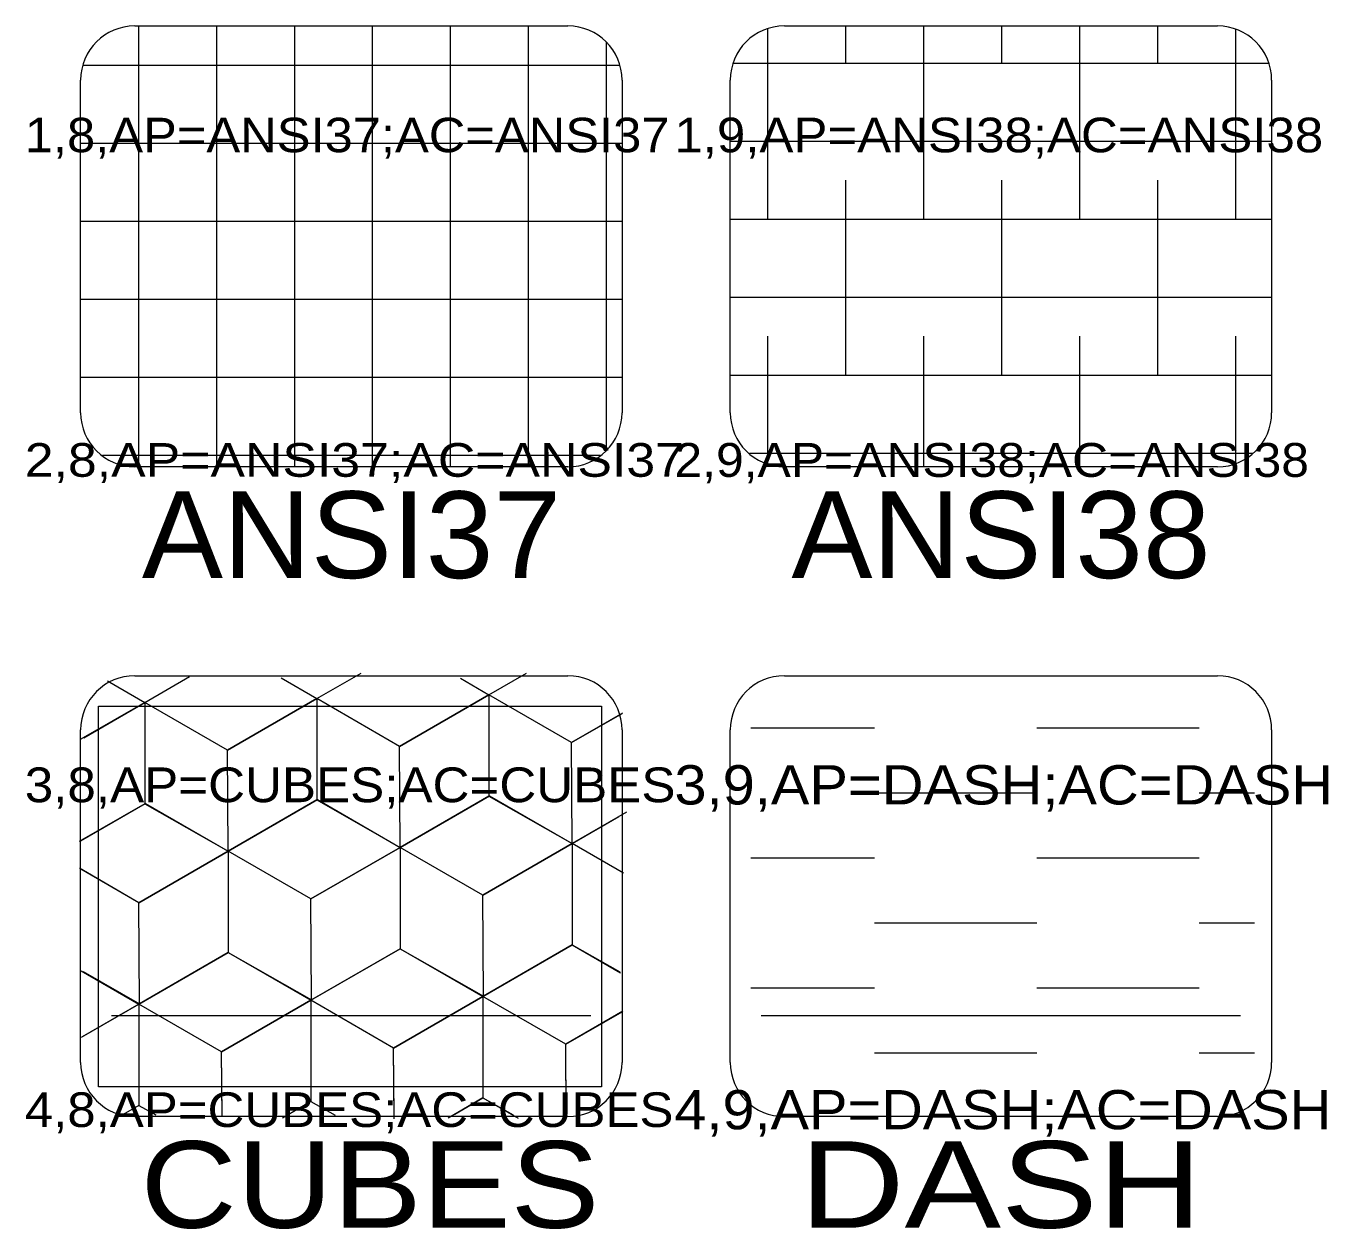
# Model space of a CAD drawing. Extents: x 95935 to 95946.4, y 95971.2 to 95974.7.
# Drawn here: x 95939.235 to 95940.433, y 95973.621 to 95974.732 of the extents above; entities that cross this region are included whole.
import ezdxf
from ezdxf.enums import TextEntityAlignment as Align

# ---------------------------------------------------------------- set-up
doc = ezdxf.new("R2010")
doc.units = 0
doc.header["$LTSCALE"] = 0.013
for name, color, linetype, lineweight in [('1', 7, 'Continuous', 13), ('25', 7, 'Continuous', 13), ('6', 7, 'Continuous', 13), ('63', 7, 'Continuous', 13)]:
    doc.layers.add(name, color=color, linetype=linetype, lineweight=lineweight)
doc.layers.add('20', color=7, linetype='Continuous')

msp = doc.modelspace()

# ---------------------------------------------------------------- linework, layer by layer
at = {"layer": '1'}
for p, q in [((95939.3357, 95974.7318), (95939.7357, 95974.7318)), ((95939.9357, 95974.7318), (95940.3357, 95974.7318)), ((95939.2857, 95974.3747), (95939.2857, 95974.6818)), ((95939.7857, 95974.6818), (95939.7857, 95974.3747)), ((95939.8857, 95974.3747), (95939.8857, 95974.6818)), ((95940.3857, 95974.6818), (95940.3857, 95974.3747)), ((95939.7357, 95974.3247), (95939.3357, 95974.3247)), ((95940.3357, 95974.3247), (95939.9357, 95974.3247)), ((95939.3357, 95974.1318), (95939.7357, 95974.1318)), ((95939.9357, 95974.1318), (95940.3357, 95974.1318)), ((95939.2857, 95973.7747), (95939.2857, 95974.0818)), ((95939.7857, 95974.0818), (95939.7857, 95973.7747)), ((95939.8857, 95973.7747), (95939.8857, 95974.0818)), ((95940.3857, 95974.0818), (95940.3857, 95973.7747)), ((95939.7357, 95973.7247), (95939.3357, 95973.7247)), ((95940.3357, 95973.7247), (95939.9357, 95973.7247))]:
    msp.add_line(p, q, dxfattribs=at)
for centre, start, end in [((95939.3357, 95974.6818), 90, 180), ((95939.7357, 95974.6818), 0, 90), ((95939.9357, 95974.6818), 90, 180), ((95940.3357, 95974.6818), 0, 90), ((95939.3357, 95974.3747), 180, 270), ((95939.7357, 95974.3747), 270, 0), ((95939.9357, 95974.3747), 180, 270), ((95940.3357, 95974.3747), 270, 0), ((95939.3357, 95974.0818), 90, 180), ((95939.7357, 95974.0818), 0, 90), ((95939.9357, 95974.0818), 90, 180), ((95940.3357, 95974.0818), 0, 90), ((95939.3357, 95973.7747), 180, 270), ((95939.7357, 95973.7747), 270, 0), ((95939.9357, 95973.7747), 180, 270), ((95940.3357, 95973.7747), 270, 0)]:
    msp.add_arc(centre, 0.05, start, end, dxfattribs=at)
at = {"layer": '25'}
for p, q in [((95939.7569, 95973.8178), (95939.3141, 95973.8178)), ((95940.3569, 95973.8178), (95939.9141, 95973.8178))]:
    msp.add_line(p, q, dxfattribs=at)
at = {"layer": '6'}
for p, q in [((95939.3391, 95974.7318), (95939.3391, 95974.3247)), ((95939.4111, 95974.7318), (95939.4111, 95974.3247)), ((95939.4831, 95974.7318), (95939.4831, 95974.3247)), ((95939.5551, 95974.7318), (95939.5551, 95974.3247)), ((95939.6271, 95974.7318), (95939.6271, 95974.3247)), ((95939.6991, 95974.7318), (95939.6991, 95974.3247)), ((95939.9205, 95974.6973), (95939.9205, 95974.7288)), ((95939.9925, 95974.6973), (95939.9925, 95974.7318)), ((95940.0645, 95974.6973), (95940.0645, 95974.7318)), ((95940.1365, 95974.6973), (95940.1365, 95974.7318)), ((95940.2085, 95974.6973), (95940.2085, 95974.7318)), ((95940.2805, 95974.6973), (95940.2805, 95974.7318)), ((95940.3525, 95974.6973), (95940.3525, 95974.7285)), ((95939.7711, 95974.7172), (95939.7711, 95974.3393)), ((95939.2884, 95974.6956), (95939.783, 95974.6956)), ((95939.8888, 95974.6973), (95940.3826, 95974.6973)), ((95939.9205, 95974.5533), (95939.9205, 95974.6973)), ((95940.0645, 95974.5533), (95940.0645, 95974.6973)), ((95940.2085, 95974.5533), (95940.2085, 95974.6973)), ((95940.3525, 95974.5533), (95940.3525, 95974.6973)), ((95939.2857, 95974.6236), (95939.7857, 95974.6236)), ((95939.8857, 95974.6253), (95940.3857, 95974.6253)), ((95939.9925, 95974.4093), (95939.9925, 95974.5893)), ((95940.1365, 95974.4093), (95940.1365, 95974.5893)), ((95940.2805, 95974.4093), (95940.2805, 95974.5893)), ((95939.2857, 95974.5516), (95939.7857, 95974.5516)), ((95939.8857, 95974.5533), (95940.3857, 95974.5533)), ((95939.2857, 95974.4796), (95939.7857, 95974.4796)), ((95939.8857, 95974.4813), (95940.3857, 95974.4813)), ((95939.9205, 95974.4093), (95939.9205, 95974.4453)), ((95940.0645, 95974.4093), (95940.0645, 95974.4453)), ((95940.2085, 95974.4093), (95940.2085, 95974.4453)), ((95940.3525, 95974.4093), (95940.3525, 95974.4453)), ((95939.2857, 95974.4076), (95939.7857, 95974.4076)), ((95939.8857, 95974.4093), (95940.3857, 95974.4093)), ((95939.9205, 95974.3277), (95939.9205, 95974.4093)), ((95940.0645, 95974.3247), (95940.0645, 95974.4093)), ((95940.2085, 95974.3247), (95940.2085, 95974.4093)), ((95940.3525, 95974.328), (95940.3525, 95974.4093)), ((95939.3059, 95974.3356), (95939.7655, 95974.3356)), ((95939.9033, 95974.3373), (95940.3681, 95974.3373)), ((95939.9048, 95974.0836), (95940.0189, 95974.0836)), ((95940.1689, 95974.0836), (95940.3189, 95974.0836)), ((95940.0189, 95974.0236), (95940.1689, 95974.0236)), ((95940.3189, 95974.0236), (95940.37, 95974.0236)), ((95939.9048, 95973.9636), (95940.0189, 95973.9636)), ((95940.1689, 95973.9636), (95940.3189, 95973.9636)), ((95940.0189, 95973.9036), (95940.1689, 95973.9036)), ((95940.3189, 95973.9036), (95940.37, 95973.9036)), ((95939.9048, 95973.8436), (95940.0189, 95973.8436)), ((95940.1689, 95973.8436), (95940.3189, 95973.8436)), ((95940.0189, 95973.7836), (95940.1689, 95973.7836)), ((95940.3189, 95973.7836), (95940.37, 95973.7836))]:
    msp.add_line(p, q, dxfattribs=at)
for points in [[(95939.3105, 95974.1272), (95939.345, 95974.1072), (95939.2858, 95974.0731)], [(95939.4709, 95974.1298), (95939.5039, 95974.1107), (95939.4214, 95974.0631), (95939.345, 95974.1072), (95939.3863, 95974.131)], [(95939.6366, 95974.1294), (95939.6628, 95974.1142), (95939.5803, 95974.0666), (95939.5039, 95974.1107), (95939.5447, 95974.1343)], [(95939.786, 95974.0972), (95939.7392, 95974.0701), (95939.6628, 95974.1142), (95939.6974, 95974.1342)], [(95939.2885, 95974.0746), (95939.345, 95974.1072), (95939.345, 95974.0136), (95939.2844, 95973.9787)], [(95939.7897, 95974.0057), (95939.7398, 95973.9768), (95939.7392, 95974.0701), (95939.7858, 95974.097)], [(95939.2858, 95973.9794), (95939.3456, 95974.0139), (95939.422, 95973.9698), (95939.3395, 95973.9222), (95939.2858, 95973.9532)], [(95939.7872, 95973.9495), (95939.7398, 95973.9768), (95939.7829, 95974.0017)], [(95939.7845, 95973.951), (95939.7398, 95973.9768), (95939.7398, 95973.8832), (95939.7838, 95973.8583)], [(95939.2879, 95973.8587), (95939.3401, 95973.8289), (95939.3395, 95973.9222), (95939.2845, 95973.954)], [(95939.7866, 95973.8221), (95939.7337, 95973.7915), (95939.6573, 95973.8356), (95939.7398, 95973.8832), (95939.7844, 95973.8575)], [(95939.2863, 95973.8594), (95939.3395, 95973.8286), (95939.2872, 95973.7985)], [(95939.2864, 95973.798), (95939.3395, 95973.8286), (95939.3395, 95973.735), (95939.325, 95973.7266)], [(95939.4164, 95973.7261), (95939.4159, 95973.7845), (95939.3395, 95973.8286), (95939.3395, 95973.735), (95939.355, 95973.7263)], [(95939.4164, 95973.7245), (95939.4159, 95973.7845), (95939.4984, 95973.8321), (95939.4984, 95973.7385), (95939.4722, 95973.7234)], [(95939.5753, 95973.7261), (95939.5748, 95973.788), (95939.4984, 95973.8321), (95939.4984, 95973.7385), (95939.5207, 95973.7259)], [(95939.5753, 95973.7225), (95939.5748, 95973.788), (95939.6573, 95973.8356), (95939.6573, 95973.742), (95939.625, 95973.7234)], [(95939.7342, 95973.7261), (95939.7337, 95973.7915), (95939.6573, 95973.8356), (95939.6573, 95973.742), (95939.6853, 95973.7262)], [(95939.7342, 95973.7243), (95939.7337, 95973.7915), (95939.7857, 95973.8215)], [(95939.6313, 95973.727), (95939.6573, 95973.742), (95939.6898, 95973.7233)]]:
    msp.add_lwpolyline(points, dxfattribs=at)
for points in [[(95939.5803, 95974.0666), (95939.6628, 95974.1142), (95939.6628, 95974.0206), (95939.5809, 95973.9733)], [(95939.7392, 95974.0701), (95939.6628, 95974.1142), (95939.6628, 95974.0206), (95939.7398, 95973.9768)], [(95939.3021, 95974.1038), (95939.7667, 95974.1038), (95939.7667, 95973.7523), (95939.3021, 95973.7523)], [(95939.4214, 95974.0631), (95939.345, 95974.1072), (95939.345, 95974.0136), (95939.422, 95973.9698)], [(95939.4214, 95974.0631), (95939.5039, 95974.1107), (95939.5039, 95974.0171), (95939.422, 95973.9698)], [(95939.5803, 95974.0666), (95939.5039, 95974.1107), (95939.5039, 95974.0171), (95939.5809, 95973.9733)], [(95939.5809, 95973.9733), (95939.6634, 95974.0209), (95939.7398, 95973.9768), (95939.6573, 95973.9292)], [(95939.422, 95973.9698), (95939.5045, 95974.0174), (95939.5809, 95973.9733), (95939.4984, 95973.9257)], [(95939.4984, 95973.9257), (95939.5809, 95973.9733), (95939.5809, 95973.8797), (95939.499, 95973.8324)], [(95939.6573, 95973.9292), (95939.5809, 95973.9733), (95939.5809, 95973.8797), (95939.6579, 95973.8359)], [(95939.6573, 95973.9292), (95939.7398, 95973.9768), (95939.7398, 95973.8832), (95939.6579, 95973.8359)], [(95939.3395, 95973.9222), (95939.422, 95973.9698), (95939.422, 95973.8762), (95939.3401, 95973.8289)], [(95939.4984, 95973.9257), (95939.422, 95973.9698), (95939.422, 95973.8762), (95939.499, 95973.8324)], [(95939.3395, 95973.8286), (95939.422, 95973.8762), (95939.4984, 95973.8321), (95939.4159, 95973.7845)], [(95939.4984, 95973.8321), (95939.5809, 95973.8797), (95939.6573, 95973.8356), (95939.5748, 95973.788)]]:
    msp.add_lwpolyline(points, close=True, dxfattribs=at)

# ---------------------------------------------------------------- texts
at = {"layer": '20'}
for s, width, p in [('ANSI37', 1.05, (95939.5358, 95974.222)), ('ANSI38', 1.05, (95940.1357, 95974.222)), (' CUBES', 1.15, (95939.5358, 95973.622)), (' DASH ', 1.25, (95940.1358, 95973.622))]:
    msp.add_text(s, height=0.08, dxfattribs=dict(at, width=width)).set_placement(p, align=Align.CENTER)
at = {"layer": '63'}
for s, height, width, p in [('1,8,AP=ANSI37;AC=ANSI37', 0.0318, 1.1, (95939.2341, 95974.6152)), ('1,9,AP=ANSI38;AC=ANSI38', 0.032, 1.1, (95939.8341, 95974.6151)), ('2,8,AP=ANSI37;AC=ANSI37', 0.0311, 1.15, (95939.2341, 95974.3155)), ('2,9,AP=ANSI38;AC=ANSI38', 0.0313, 1.1, (95939.8341, 95974.3154)), ('3,8,AP=CUBES;AC=CUBES', 0.0321, 1.1, (95939.2341, 95974.015)), ('3,9,AP=DASH;AC=DASH', 0.0363, 1.1, (95939.8341, 95974.0129)), ('4,8,AP=CUBES;AC=CUBES', 0.032, 1.1, (95939.2341, 95973.7151)), ('4,9,AP=DASH;AC=DASH', 0.0362, 1.1, (95939.8341, 95973.713))]:
    msp.add_text(s, height=height, dxfattribs=dict(at, width=width)).set_placement(p)

doc.saveas('drawing.dxf')
